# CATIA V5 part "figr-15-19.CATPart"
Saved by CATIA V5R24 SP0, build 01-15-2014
Part number: Part1
Bounding box of the stored display mesh (mm): x -46.56 to 46.56, y -36.965 to 25.965, z 0 to 40
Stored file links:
  D:\KAVITA\CATIA V5-6R2014 Project_ Kavita\CATIA V5-6R2014_partfiles\Partfiles\c15_catia_v5-6r2014_prt\figr-15-19.CATPart
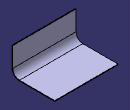
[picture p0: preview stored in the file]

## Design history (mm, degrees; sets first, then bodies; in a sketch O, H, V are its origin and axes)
SheetMetalParameters1: Thickness 1, BendRadius 1, KFactor 0.325257 {= log(min(100,max(20*SheetMetalParameters1.BendRadius,SheetMetalParameters1.Thickness)/SheetMetalParameters1.Thickness))/log(100)/2}, ReliefRadialLength 1, ReliefAxialLength 2, MinimumBendRadius 0
Body1 (main body)
  Sketch1 on xy-plane, origin (0, 0, 0), H (1, 0, 0), V (0, 1, 0)
    line L1 (-46.5596, 25.9646) -> (46.5596, 25.9646)
    line L2 (46.5596, 25.9646) -> (46.5596, -25.9646)
    line L3 (46.5596, -25.9646) -> (-46.5596, -25.9646)
    line L4 (-46.5596, -25.9646) -> (-46.5596, 25.9646)
    horizontal: L1 H, L3 H
    vertical: L2 V, L4 V
    symmetry: L1 L3 H, L4 L2 V
  Wall1: Thickness 1, Profile Sketch1
  d_NewWallOnEdge1: NewWallOnEdge_Edge edge [face of Wall1 | face of Wall1], NewWallOnEdge_Length 40, NewWallOnEdge_HeightLimitOffset 0, NewWallOnEdge_WidthOffset1 0, NewWallOnEdge_WidthOffset2 0, NewWallOnEdge_Angle 90, NewWallOnEdge_BendRadiusValue 10 {= d_NewWallOnEdge1.Clearance}, NewWallOnEdge_BendTable SheetMetalParameters1, KFacteur 0.5 {= log(min(100,max(20*d_NewWallOnEdge1.Radius,SheetMetalParameters1.Thickness)/SheetMetalParameters1.Thickness))/log(100)/2}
